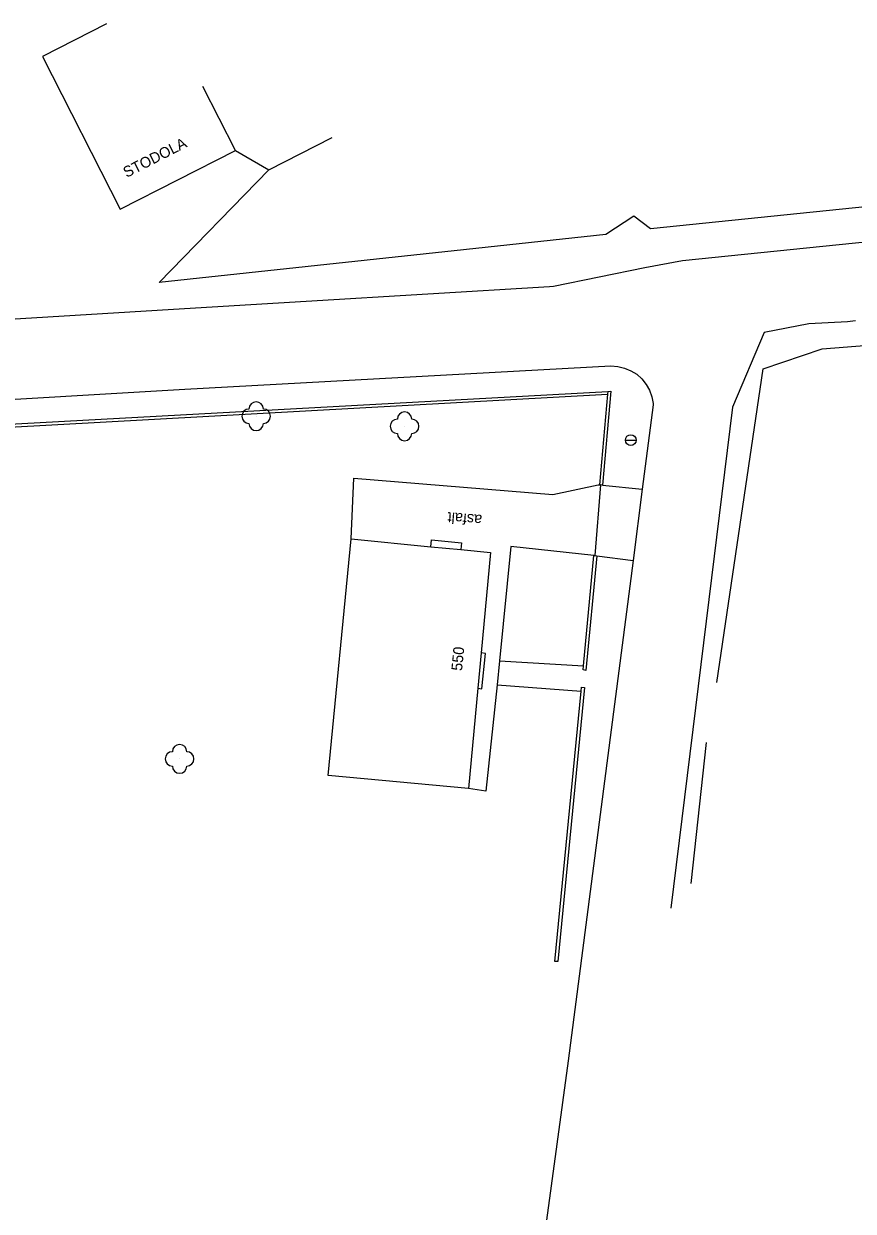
# Model space of a CAD drawing. Extents: x -536391 to -535419, y -1201788 to -1200779.
# Drawn here: x -535647.8 to -535590.1, y -1201668.6 to -1201586 of the extents above; entities that cross this region are included whole.
import ezdxf

# ---------------------------------------------------------------- set-up
doc = ezdxf.new("R2010")
doc.units = 0
for name, color, linetype in [('CIZÍ_NADZEM_POPIS', 7, 'Continuous'), ('CIZÍ_PODZEM_POPIS', 7, 'Continuous'), ('KONEC_VEDENÍ', 7, 'Continuous'), ('POL_ZNAČKA_PRACOVNÍ', 7, 'Continuous'), ('SDEL_EON_POPIS', 7, 'Continuous'), ('TECH_OCHR_PÁSMO_HRAN', 7, 'Continuous')]:
    doc.layers.add(name, color=color, linetype=linetype)

msp = doc.modelspace()

# ---------------------------------------------------------------- linework, layer by layer
at = {"layer": 'CIZÍ_PODZEM_POPIS'}
msp.add_line((-535605.935, -1201614.93), (-535605.185, -1201614.93), dxfattribs=at)
for points in [[(-535572.12, -1201588.65), (-535571.35, -1201590.42), (-535577.76, -1201593.75), (-535587.2, -1201598.48), (-535604.18, -1201600.22)], [(-535630.75, -1201596.13), (-535626.34, -1201593.87)], [(-535633.08, -1201594.77), (-535630.75, -1201596.13)], [(-535604.18, -1201600.22), (-535605.35, -1201599.35), (-535607.29, -1201600.63), (-535617.85, -1201601.75), (-535638.39, -1201603.96), (-535630.75, -1201596.13)], [(-535592.23, -1201608.58), (-535584.33, -1201607.95), (-535556.13, -1201605.24)], [(-535599.58, -1201631.8), (-535596.35, -1201609.97), (-535592.23, -1201608.58)], [(-535649.24, -1201614.05), (-535607.18, -1201611.74)], [(-535649.22, -1201613.85), (-535607.16, -1201611.54)], [(-535607.18, -1201611.74), (-535607.73, -1201618.04)], [(-535607.16, -1201611.54), (-535606.96, -1201611.53), (-535607.53, -1201618.06)], [(-535607.16, -1201611.54), (-535607.18, -1201611.74)], [(-535608.04, -1201622.97), (-535607.64, -1201618.05)], [(-535607.73, -1201618.04), (-535607.64, -1201618.05)], [(-535607.53, -1201618.06), (-535607.64, -1201618.05)], [(-535607.93, -1201622.98), (-535608.68, -1201630.95), (-535608.88, -1201630.92), (-535608.85, -1201630.64)], [(-535608.85, -1201630.64), (-535608.13, -1201622.96)], [(-535608.13, -1201622.96), (-535608.04, -1201622.97)], [(-535608.04, -1201622.97), (-535607.93, -1201622.98)], [(-535610.64, -1201651.2), (-535610.84, -1201651.21), (-535609.02, -1201632.39)], [(-535609.02, -1201632.39), (-535608.99, -1201632.12), (-535608.79, -1201632.14), (-535610.64, -1201651.2)], [(-535601.35, -1201645.78), (-535600.29, -1201635.98)]]:
    msp.add_lwpolyline(points, dxfattribs=at)
msp.add_circle((-535605.56, -1201614.93), 0.375, dxfattribs=at)
at = {"layer": 'KONEC_VEDENÍ'}
for centre in [(-535631.64, -1201613.27), (-535621.31, -1201613.97), (-535636.97, -1201637.11)]:
    msp.add_circle(centre, 0.0005, dxfattribs=at)
for centre, start, end in [((-535631.64, -1201612.77), 0, 179.99999), ((-535632.14, -1201613.27), 89.99999, 269.99999), ((-535631.14, -1201613.27), 270, 89.99999), ((-535621.81, -1201613.97), 89.99999, 269.99999), ((-535621.31, -1201613.47), 0, 179.99999), ((-535620.81, -1201613.97), 270, 89.99999), ((-535631.64, -1201613.77), 179.99999, 359.99999), ((-535621.31, -1201614.47), 179.99999, 359.99999), ((-535637.47, -1201637.11), 89.99999, 269.99999), ((-535636.97, -1201636.61), 0, 179.99999), ((-535636.47, -1201637.11), 270, 89.99999), ((-535636.97, -1201637.61), 179.99999, 359.99999)]:
    msp.add_arc(centre, 0.5, start, end, dxfattribs=at)
at = {"layer": 'SDEL_EON_POPIS'}
for points in [[(-535642.06, -1201585.96), (-535646.51, -1201588.24), (-535641.1, -1201598.86), (-535633.08, -1201594.77)], [(-535633.08, -1201594.77), (-535635.36, -1201590.32)], [(-535616.86, -1201639.18), (-535626.62, -1201638.27), (-535625.02, -1201621.81)], [(-535625.02, -1201621.81), (-535619.47, -1201622.35)], [(-535619.47, -1201622.35), (-535617.4, -1201622.55)], [(-535617.4, -1201622.55), (-535615.32, -1201622.75), (-535615.98, -1201629.74)], [(-535615.98, -1201629.74), (-535616.21, -1201632.2)], [(-535616.21, -1201632.2), (-535616.86, -1201639.18)]]:
    msp.add_lwpolyline(points, dxfattribs=at)
at = {"layer": 'TECH_OCHR_PÁSMO_HRAN'}
for points in [[(-535586.73, -1201600.91), (-535601.96, -1201602.45), (-535604.58, -1201602.94), (-535610.94, -1201604.25), (-535611.21, -1201604.27), (-535636.62, -1201605.79), (-535670.91, -1201607.88)], [(-535593.16, -1201606.83), (-535596.27, -1201607.45), (-535598.47, -1201612.63), (-535600.88, -1201632.06), (-535602.77, -1201647.49)], [(-535589.91, -1201606.63), (-535590.1, -1201606.65), (-535590.29, -1201606.67), (-535590.47, -1201606.69), (-535593.16, -1201606.83)], [(-535670.5, -1201613.38), (-535636.6, -1201611.38), (-535606.94, -1201609.77), (-535606.46, -1201609.81), (-535605.99, -1201609.92), (-535605.55, -1201610.1), (-535605.15, -1201610.35), (-535604.79, -1201610.67), (-535604.49, -1201611.05), (-535604.25, -1201611.46), (-535604.09, -1201611.92), (-535604.01, -1201612.39), (-535604, -1201612.47), (-535604.76, -1201618.34)], [(-535625.02, -1201621.81), (-535624.85, -1201617.57), (-535610.99, -1201618.72), (-535607.83, -1201618.05), (-535607.73, -1201618.04)], [(-535607.53, -1201618.06), (-535604.76, -1201618.34)], [(-535604.76, -1201618.34), (-535605.4, -1201623.3)], [(-535619.47, -1201622.35), (-535619.43, -1201621.87), (-535617.35, -1201622.07), (-535617.4, -1201622.55)], [(-535608.13, -1201622.96), (-535613.9, -1201622.33), (-535614.7, -1201630.29)], [(-535605.4, -1201623.3), (-535609.91, -1201658.13), (-535616.63, -1201707.41), (-535624.28, -1201765.57), (-535626.89, -1201785.62), (-535627.19, -1201786.05), (-535627.78, -1201786.76), (-535628.42, -1201787.43), (-535629.12, -1201788.03), (-535629.31, -1201788.17)], [(-535607.93, -1201622.98), (-535605.4, -1201623.3)], [(-535616.21, -1201632.2), (-535615.92, -1201632.23), (-535615.68, -1201629.77), (-535615.98, -1201629.74)], [(-535614.7, -1201630.29), (-535614.85, -1201631.95)], [(-535614.7, -1201630.29), (-535608.85, -1201630.64)], [(-535614.85, -1201631.95), (-535615.65, -1201639.36), (-535616.86, -1201639.18)], [(-535614.85, -1201631.95), (-535609.02, -1201632.39)]]:
    msp.add_lwpolyline(points, dxfattribs=at)

# ---------------------------------------------------------------- texts
at = {"layer": 'CIZÍ_NADZEM_POPIS'}
msp.add_text('550', height=0.75, rotation=84.40001, dxfattribs=at).set_placement((-535617.31, -1201631.01))
at = {"layer": 'POL_ZNAČKA_PRACOVNÍ'}
for s, rotation, p in [('STODOLA', 27.04, (-535640.66, -1201596.69)), ('asfalt', 175.26, (-535615.89, -1201620.14))]:
    msp.add_text(s, height=0.75, rotation=rotation, dxfattribs=at).set_placement(p)

doc.saveas('drawing.dxf')
